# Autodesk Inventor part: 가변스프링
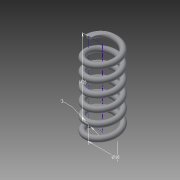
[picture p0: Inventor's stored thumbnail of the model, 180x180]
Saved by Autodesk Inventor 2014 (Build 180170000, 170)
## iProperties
Created: 2015-12
Part Number: 가변스프링
Material: Generic
Document SubType Name: Modeling
Designer: test_01
Density: 1 g/cm^3
Appearance: Default
Mass: 2.09954 g
Surface Area: 28.4907 cm^2
Volume: 2.09954 cm^3
Author: test_01
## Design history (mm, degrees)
sketch "스케치1"
  geometry: L1 (0, 0)-(8, 0); L2 (8, 0)-(8, 42); L3 (8, 42)-(0, 42); L4 (0, 42)-(0, 0); C1 r 1.5 at (8, 0)
  constraints: 8 end point, 2 parallel, 1 centre point, 1 coincident, 1 horizontal, 1 perpendicular
  dimensions: "d0" = 16 diameter of L2 L4; "d1" = 42 distance of L1.end L2.end (derived); "d2" = 3 diameter of C1
feature "코일1" pitch "d3" = 10; turns "d5" = 6; dims "d4" = 42 (= d1), "d6" = 0, angle "d7" = 90 deg, angle "d8" = 90 deg, "d9" = 0, "d10" = 0
sketch "스케치2"
  geometry: L1 (-9.5, 0)-(-6.5, 0) reference; 1 further point
  constraints: 1 horizontal alignment
extrude "돌출1" cut sketch "스케치2" distance "d11" = 10; taper "d12" = 0 deg
node "작업 평면1"
sketch "스케치3"
  geometry: L1 (-1.5, 0)-(1.5, 0) reference; 1 further point
  constraints: 1 horizontal alignment
extrude "돌출2" cut sketch "스케치3" distance "d14" = 10; taper "d15" = 0 deg
node "솔리드1"
node "절단 모서리 투영1"
node "절단 모서리 투영2"
other parameters: "d13" = 90 deg
